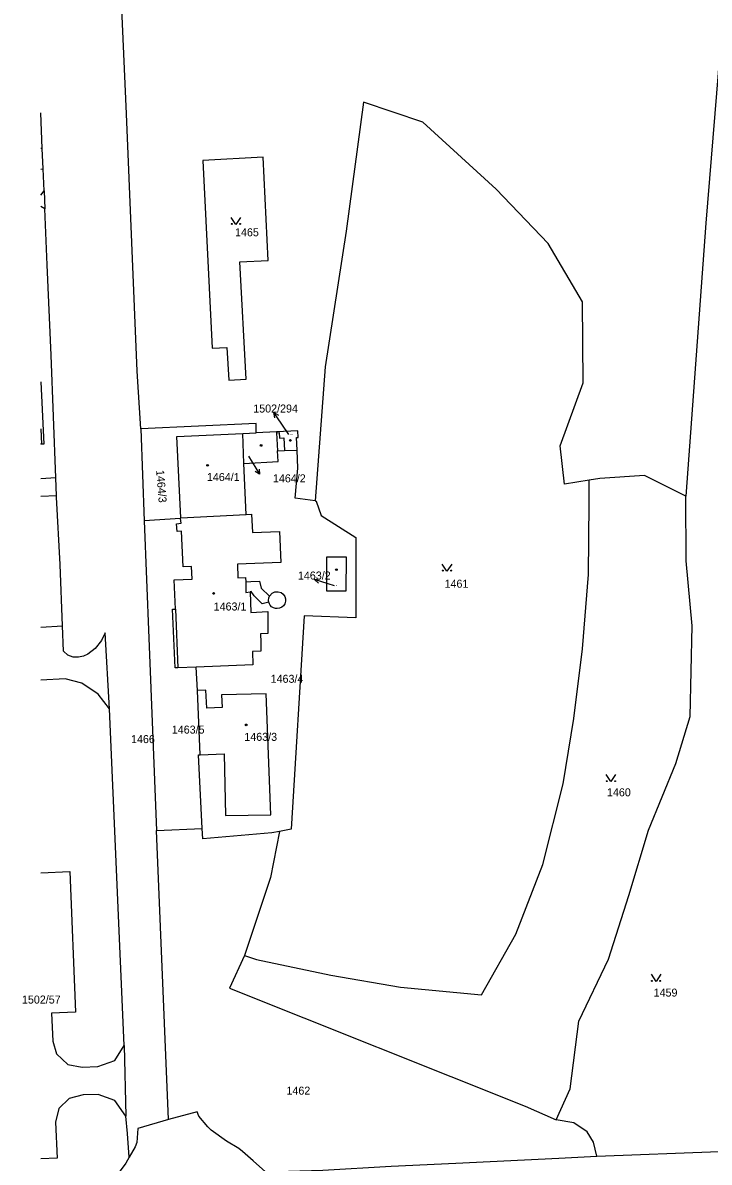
# Model space of a CAD drawing. Extents: x -736397 to -735924, y -1118983 to -1118245.
# Drawn here: x -736392.7 to -736247, y -1118835.5 to -1118593.4 of the extents above; entities that cross this region are included whole.
import ezdxf

# ---------------------------------------------------------------- set-up
doc = ezdxf.new("R2010")
doc.units = 0
for name, color, linetype in [('Vrstva 1', 7, 'Continuous'), ('Vrstva 16', 7, 'Continuous'), ('Vrstva 18', 7, 'Continuous'), ('Vrstva 19', 7, 'Continuous'), ('Vrstva 25', 7, 'Continuous'), ('Vrstva 4', 7, 'Continuous')]:
    doc.layers.add(name, color=color, linetype=linetype)

msp = doc.modelspace()

# ---------------------------------------------------------------- linework, layer by layer
at = {"layer": 'Vrstva 1'}
for p, q in [((-736388.39, -1118624.48), (-736388.58, -1118620.14)), ((-736388.19, -1118629.1), (-736388.39, -1118624.48)), ((-736388.19, -1118629.1), (-736388.03, -1118632.93)), ((-736367.65, -1118679.7), (-736366.94, -1118699.23)), ((-736345.96, -1118680.68), (-736343.19, -1118680.54)), ((-736345.76, -1118687.02), (-736345.96, -1118680.68)), ((-736338.84, -1118680.34), (-736343.19, -1118680.54)), ((-736338.84, -1118680.34), (-736338.83, -1118680.52)), ((-736338.83, -1118680.52), (-736338.63, -1118684.37)), ((-736388.9, -1118682.97), (-736388.91, -1118682.97)), ((-736388.76, -1118682.96), (-736388.9, -1118682.97)), ((-736338.63, -1118684.37), (-736337.16, -1118684.29)), ((-736337.16, -1118684.29), (-736334.47, -1118684.19)), ((-736345.29, -1118697.91), (-736345.76, -1118687.02)), ((-736385.53, -1118693.9), (-736385.71, -1118690.13)), ((-736359.21, -1118698.75), (-736366.94, -1118699.23)), ((-736359.21, -1118698.75), (-736359.17, -1118698.56)), ((-736359.17, -1118698.56), (-736345.29, -1118697.91)), ((-736355.92, -1118730.34), (-736359.77, -1118730.48)), ((-736355.61, -1118735.28), (-736355.92, -1118730.34)), ((-736355.02, -1118748.91), (-736355.61, -1118735.28)), ((-736371.2, -1118810.67), (-736374.31, -1118739.15)), ((-736364.3, -1118764.99), (-736354.61, -1118764.6)), ((-736361.77, -1118826.39), (-736364.3, -1118764.99)), ((-736371.2, -1118810.67), (-736370.8, -1118825.72))]:
    msp.add_line(p, q, dxfattribs=at)
for points in [[(-736227.49, -1118462.99), (-736228.6, -1118463.11), (-736230.07, -1118469.05), (-736237.36, -1118522.21), (-736239.9, -1118543.95), (-736244.25, -1118594.56), (-736247.64, -1118635.96), (-736251.91, -1118694.01)], [(-736367.65, -1118679.7), (-736368.4, -1118667.4), (-736370.7, -1118612.79), (-736372.92, -1118563.37), (-736374.05, -1118539.63)], [(-736272.41, -1118690.57), (-736277.67, -1118691.42), (-736278.63, -1118683.27), (-736273.72, -1118669.94), (-736273.88, -1118652.68), (-736281.15, -1118640.28), (-736292.18, -1118628.77), (-736307.76, -1118614.54), (-736320.35, -1118610.31), (-736324.04, -1118637.7), (-736328.53, -1118666.52), (-736330.6, -1118695)], [(-736388.58, -1118620.14), (-736388.91, -1118612.52)], [(-736388.58, -1118620.14), (-736388.91, -1118620.15)], [(-736340.61, -1118643.95), (-736341.64, -1118621.99), (-736354.46, -1118622.69), (-736352.5, -1118662.58), (-736349.35, -1118662.41), (-736348.98, -1118669.33), (-736345.27, -1118669.13), (-736346.6, -1118644.23), (-736340.61, -1118643.95)], [(-736388.91, -1118624.49), (-736388.39, -1118624.48)], [(-736388.91, -1118630.06), (-736388.19, -1118629.1)], [(-736388.03, -1118632.93), (-736388.91, -1118632.47)], [(-736385.71, -1118690.13), (-736386.66, -1118664.01), (-736387.51, -1118644.88), (-736388.03, -1118632.93)], [(-736388.91, -1118669.73), (-736388.86, -1118669.73), (-736388.26, -1118682.94), (-736388.76, -1118682.96)], [(-736343.19, -1118680.54), (-736343.14, -1118678.55), (-736367.65, -1118679.7)], [(-736359.17, -1118698.56), (-736360.02, -1118681.32), (-736345.96, -1118680.68)], [(-736334.47, -1118684.19), (-736334.6, -1118681.51), (-736334.22, -1118681.53), (-736334.29, -1118680.12), (-736338.84, -1118680.34)], [(-736345.76, -1118687.02), (-736338.5, -1118686.61), (-736338.63, -1118684.37)], [(-736330.6, -1118695), (-736334.88, -1118694.41), (-736334.28, -1118688.05), (-736334.47, -1118684.19)], [(-736385.71, -1118690.13), (-736388.91, -1118690.3)], [(-736345.65, -1118791.54), (-736343.12, -1118792.42), (-736327.32, -1118795.74), (-736312.51, -1118798.28), (-736295.32, -1118799.91), (-736288.05, -1118787.01), (-736282.26, -1118772.21), (-736277.99, -1118755.13), (-736275.67, -1118741.24), (-736273.83, -1118726.39), (-736272.58, -1118710.63), (-736272.45, -1118695.47), (-736272.41, -1118690.57)], [(-736251.91, -1118694.01), (-736260.66, -1118689.58), (-736270.2, -1118690.22), (-736272.41, -1118690.57)], [(-736385.53, -1118693.9), (-736388.91, -1118694.04)], [(-736384.29, -1118721.54), (-736384.79, -1118708.52), (-736385.52, -1118694.17), (-736385.53, -1118693.9)], [(-736279.42, -1118826.51), (-736276.51, -1118819.91), (-736274.67, -1118805.5), (-736268.32, -1118792.34), (-736264.01, -1118778.85), (-736259.87, -1118764.94), (-736254.03, -1118750.79), (-736250.98, -1118740.81), (-736250.57, -1118721.52), (-736251.84, -1118707.7), (-736251.91, -1118694.01)], [(-736330.6, -1118695), (-736330.44, -1118695.03), (-736329.36, -1118698.11), (-736322, -1118702.76), (-736321.98, -1118719.87), (-736332.98, -1118719.42), (-736335.71, -1118764.72), (-736338.17, -1118765.21)], [(-736366.94, -1118699.23), (-736365.97, -1118724.19), (-736364.3, -1118764.99)], [(-736360.3, -1118717.97), (-736360.56, -1118711.77), (-736356.77, -1118711.63), (-736356.89, -1118708.9), (-736358.69, -1118708.98), (-736359.02, -1118701.44), (-736359.96, -1118701.48), (-736360.05, -1118699.84), (-736359.09, -1118699.75), (-736359.21, -1118698.75)], [(-736345.29, -1118697.91), (-736344.13, -1118697.81), (-736343.93, -1118701.73), (-736338.22, -1118701.49), (-736337.95, -1118708.06), (-736347.1, -1118708.44), (-736347.05, -1118711.34), (-736345.39, -1118711.25), (-736345.33, -1118712.19)], [(-736328.2, -1118706.92), (-736328.21, -1118714.09), (-736324.03, -1118714.08), (-736323.99, -1118706.92), (-736328.2, -1118706.92)], [(-736345.33, -1118712.19), (-736344.31, -1118712.15), (-736342.42, -1118712.07), (-736342.06, -1118713.55), (-736340.32, -1118715.2)], [(-736344.44, -1118714.32), (-736344.27, -1118718.67), (-736340.66, -1118718.51), (-736340.65, -1118723.14), (-736342.21, -1118723.27), (-736342.18, -1118724.98), (-736342.14, -1118726.9), (-736343.95, -1118726.97), (-736343.84, -1118729.85), (-736355.92, -1118730.34)], [(-736340.47, -1118716.5), (-736341.88, -1118716.84), (-736343.61, -1118715.19), (-736344.21, -1118714.27), (-736344.44, -1118714.32)], [(-736340.32, -1118715.2), (-736339.79, -1118714.62), (-736339.18, -1118714.33), (-736338.49, -1118714.28), (-736337.85, -1118714.49), (-736337.41, -1118714.82), (-736337.08, -1118715.3), (-736336.93, -1118715.79), (-736336.92, -1118716.3), (-736337.08, -1118716.84), (-736337.37, -1118717.28), (-736337.7, -1118717.57), (-736338.17, -1118717.8), (-736338.69, -1118717.88), (-736339.07, -1118717.85), (-736339.51, -1118717.7), (-736339.87, -1118717.47), (-736340.15, -1118717.17), (-736340.35, -1118716.84), (-736340.47, -1118716.5)], [(-736359.77, -1118730.48), (-736360.35, -1118730.49), (-736360.9, -1118717.97), (-736360.3, -1118717.97)], [(-736388.91, -1118721.84), (-736384.29, -1118721.54)], [(-736374.31, -1118739.15), (-736375.23, -1118723.02), (-736376, -1118724.68), (-736377.32, -1118726.32), (-736378.9, -1118727.52), (-736379.79, -1118728.01), (-736380.87, -1118728.2), (-736382.04, -1118728.21), (-736383.15, -1118727.75), (-736384.09, -1118726.92), (-736384.29, -1118721.54)], [(-736374.31, -1118739.15), (-736376.7, -1118736.05), (-736380.17, -1118733.71), (-736383.73, -1118732.83), (-736388.91, -1118733.06)], [(-736355.02, -1118748.91), (-736349.94, -1118748.7), (-736349.69, -1118761.83), (-736340.05, -1118761.7), (-736341, -1118735.99), (-736350.51, -1118736.17), (-736350.4, -1118738.92), (-736353.65, -1118739.06), (-736353.82, -1118735.22), (-736355.61, -1118735.28)], [(-736354.61, -1118764.6), (-736355.38, -1118748.97), (-736355.02, -1118748.91)], [(-736338.17, -1118765.21), (-736339.8, -1118765.53), (-736354.5, -1118766.82), (-736354.61, -1118764.6)], [(-736338.17, -1118765.21), (-736340.14, -1118775.03), (-736345.65, -1118791.54)], [(-736388.91, -1118774), (-736382.73, -1118773.7), (-736381.51, -1118803.61), (-736386.59, -1118803.84), (-736386.36, -1118809.74), (-736385.56, -1118812.49), (-736383.17, -1118814.7), (-736380.12, -1118815.31), (-736376.76, -1118815.13), (-736373.16, -1118813.91), (-736371.2, -1118810.67)], [(-736345.65, -1118791.54), (-736348.83, -1118798.49), (-736286.05, -1118823.6), (-736279.42, -1118826.51)], [(-736370.8, -1118825.72), (-736373.17, -1118822.4), (-736376.74, -1118821.1), (-736379.88, -1118821.16), (-736382.83, -1118821.97), (-736385.03, -1118824.1), (-736385.77, -1118827), (-736385.4, -1118834.62), (-736388.91, -1118834.76)], [(-736341.17, -1118837.53), (-736343.79, -1118835.17), (-736346.04, -1118833.2), (-736346.85, -1118832.56), (-736349.46, -1118831.04), (-736352.7, -1118828.71), (-736353.4, -1118828), (-736355.31, -1118825.68), (-736355.71, -1118824.8), (-736361.77, -1118826.39)], [(-736370.1, -1118834.4), (-736370.5, -1118829.41), (-736370.8, -1118825.72)], [(-736361.77, -1118826.39), (-736368.29, -1118828.31), (-736368.41, -1118830.33), (-736368.52, -1118831.3), (-736368.86, -1118832.23), (-736370.1, -1118834.4)], [(-736270.78, -1118834.19), (-736271.49, -1118831.26), (-736272.87, -1118829.05), (-736275.67, -1118827.13), (-736279.42, -1118826.51)], [(-736370.1, -1118834.4), (-736370.84, -1118835.71), (-736372.06, -1118837.33), (-736373.5, -1118838.72), (-736376.06, -1118840.27), (-736377.91, -1118841.08), (-736380.52, -1118841.65), (-736382.8, -1118841.95), (-736388.91, -1118842.44)], [(-736341.17, -1118837.53), (-736329.03, -1118837.15), (-736314.51, -1118836.31), (-736300.78, -1118835.7), (-736278.9, -1118834.59), (-736270.78, -1118834.19)], [(-736270.78, -1118834.19), (-736244.82, -1118833.2), (-736233.37, -1118832.85)]]:
    msp.add_lwpolyline(points, dxfattribs=at)
at = {"layer": 'Vrstva 16'}
for points in [[(-736339.22, -1118677.33), (-736339.37, -1118676.22), (-736338.39, -1118676.77)], [(-736336.22, -1118680.89), (-736337.69, -1118678.71), (-736339.37, -1118676.22)], [(-736344.76, -1118685.49), (-736343.98, -1118686.79), (-736342.43, -1118689.35)], [(-736342.52, -1118688.24), (-736342.43, -1118689.35), (-736343.37, -1118688.76)], [(-736329.94, -1118712.48), (-736330.74, -1118711.7), (-736329.63, -1118711.53)], [(-736326.51, -1118713.05), (-736327.88, -1118712.61), (-736330.74, -1118711.7)]]:
    msp.add_lwpolyline(points, dxfattribs=at)
at = {"layer": 'Vrstva 25'}
for points in [[(-736346.45, -1118634.76), (-736347.45, -1118636.26), (-736348.45, -1118634.76)], [(-736301.64, -1118708.41), (-736302.64, -1118709.91), (-736303.64, -1118708.41)], [(-736266.82, -1118753.14), (-736267.82, -1118754.64), (-736268.82, -1118753.14)], [(-736257.23, -1118795.56), (-736258.23, -1118797.06), (-736259.23, -1118795.56)]]:
    msp.add_lwpolyline(points, dxfattribs=at)
for centre in [(-736348.35, -1118636.16), (-736346.55, -1118636.16), (-736303.54, -1118709.81), (-736301.74, -1118709.81), (-736268.72, -1118754.54), (-736266.92, -1118754.54), (-736259.13, -1118796.96), (-736257.33, -1118796.96)]:
    msp.add_circle(centre, 0.1, dxfattribs=at)
for centre in [(-736335.9, -1118682.16), (-736342.11, -1118683.22), (-736353.48, -1118687.44), (-736326.1, -1118709.6), (-736352.19, -1118714.65), (-736345.26, -1118742.57)]:
    msp.add_ellipse(centre, major_axis=(0.18, 0), ratio=0.984808, dxfattribs=at)
at = {"layer": 'Vrstva 4'}
for p, q in [((-736388.91, -1118679.68), (-736388.76, -1118682.96)), ((-736360.3, -1118717.97), (-736359.77, -1118730.48))]:
    msp.add_line(p, q, dxfattribs=at)
for points in [[(-736338.83, -1118680.52), (-736338.24, -1118680.49), (-736338.18, -1118681.68), (-736337.3, -1118681.63), (-736337.16, -1118684.29)], [(-736388.91, -1118682.77), (-736388.9, -1118682.97)], [(-736345.33, -1118712.19), (-736345.32, -1118714.42), (-736344.44, -1118714.32)], [(-736340.47, -1118716.5), (-736340.52, -1118716.15), (-736340.45, -1118715.56), (-736340.32, -1118715.2)]]:
    msp.add_lwpolyline(points, dxfattribs=at)

# ---------------------------------------------------------------- texts
at = {"layer": 'Vrstva 16'}
for s, p in [('1502/294', (-736343.77, -1118676.22)), ('1464/2', (-736339.59, -1118691.05)), ('1463/2', (-736334.29, -1118711.7)), ('1466', (-736369.73, -1118746.45))]:
    msp.add_text(s, height=1.7, dxfattribs=at).set_placement(p)
at = {"layer": 'Vrstva 18'}
for s, p in [('1465', (-736347.64, -1118638.78)), ('1461', (-736303.15, -1118713.44)), ('1463/4', (-736340.08, -1118733.64)), ('1463/5', (-736361.07, -1118744.43)), ('1460', (-736268.66, -1118757.75)), ('1502/57', (-736392.89, -1118801.78)), ('1459', (-736258.75, -1118800.3)), ('1462', (-736336.72, -1118821.13))]:
    msp.add_text(s, height=1.7, dxfattribs=at).set_placement(p)
msp.add_text('1464/3', height=1.7, rotation=274.6881, dxfattribs=at).set_placement((-736364.4, -1118688.5))
at = {"layer": 'Vrstva 19'}
for s, height, p in [('1502/294', 0.1, (-736335.99, -1118680.89)), ('1464/2', 0.1, (-736344.59, -1118685.49)), ('1464/1', 1.7, (-736353.61, -1118690.77)), ('1463/2', 0.1, (-736326.34, -1118713.05)), ('1463/1', 1.7, (-736352.18, -1118718.28)), ('1463/3', 1.7, (-736345.67, -1118745.97))]:
    msp.add_text(s, height=height, dxfattribs=at).set_placement(p)

doc.saveas('drawing.dxf')
